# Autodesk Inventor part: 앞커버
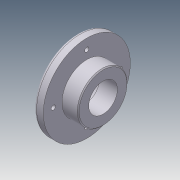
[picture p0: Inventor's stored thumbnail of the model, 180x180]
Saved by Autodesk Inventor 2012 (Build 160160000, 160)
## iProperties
Company: 한국ATC센터
Created: 2014-11
Part Number: 앞커버
Document SubType Name: Modeling
Designer: KYOUNG IL JANG
Density: 2.71 g/cm^3
Material: 알루미늄-6061
Mass: 204.895 g
Surface Area: 201.401 cm^2
Volume: 75.6071 cm^3
Author: KYOUNG IL JANG
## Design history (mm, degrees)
sketch "스케치1"
  geometry: L1 (-13.5, 0)-(13.5, 0); L2 (-13.5, 0)-(-13.5, 45.5); L3 (-13.5, 45.5)-(-3.5, 45.5); L4 (-3.5, 45.5)-(-3.5, 26); L5 (-3.5, 26)-(13.5, 26); L6 (13.5, 26)-(13.5, 0); 2 further points
  constraints: 12 end point, 3 parallel, 2 perpendicular, 1 coincident, 1 horizontal, 1 midpoint
  dimensions: "d0" = 27 distance of L1.start L1.end; "d1" = 91 diameter of L3 L1; "d2" = 52 diameter of L5 L1; "d3" = 10 distance of L2.end L3.end
revolve "회전1" sketch "스케치1" stored, may be unused: angle "d4" = 90 deg
hole "구멍1" diameter "d7" = 30; stored, may be unused: countersink angle "d11" = 90 deg, drill point angle "d13" = 118 deg; dims "d5" = 10, "d6" = 10, "d8" = 6, "d9" = 40, "d10" = 8.3, "d12" = 8
sketch "스케치2"
  geometry: 2 further points
  constraints: 1 vertical alignment
  dimensions: "d14" = 35 distance of point (0, 0) point (0, 35)
hole "구멍2" sketch "스케치2" at (0, 35) diameter "d15" = 4.5; stored, may be unused: countersink angle "d19" = 90 deg, drill point angle "d21" = 118 deg; dims "d16" = 6, "d17" = 8, "d18" = 4.4, "d20" = 8
chamfer "모따기1" distance "d25" = 0.8; stored, may be unused: second distance "d26" = 2, angle "d27" = 30 deg
fillet "모깎기1" dims "d28" = 0.3, "d29" = 3
chamfer "모따기2" distance "d30" = 1; stored, may be unused: second distance "d31" = 2, angle "d32" = 30 deg
node "솔리드1"
pattern_circular "원형 패턴1" dims angle "d23" = 360 deg
